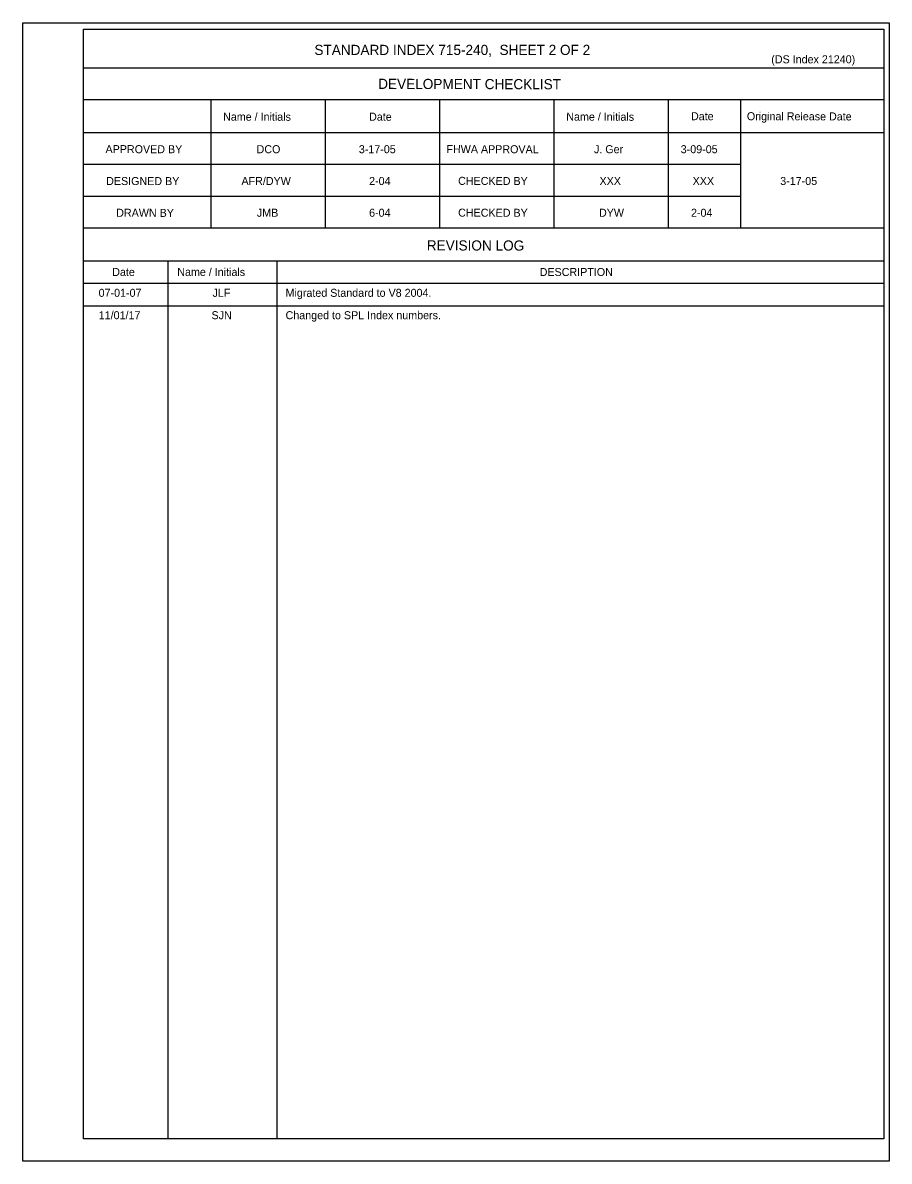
# Model space of a CAD drawing. Extents: x 112544 to 112597.1, y 111084 to 111107.1.
# Drawn here: x 112580.73 to 112597.09, y 111084.01 to 111105.51 of the extents above; entities that cross this region are included whole.
import ezdxf

# ---------------------------------------------------------------- set-up
doc = ezdxf.new("R2010")
doc.units = 0
for name, color, linetype in [('Border', 7, 'Continuous'), ('Dimension', 7, 'Continuous'), ('PlotBorder_dp', 7, 'Continuous'), ('TextStructures', 7, 'Continuous')]:
    doc.layers.add(name, color=color, linetype=linetype)

msp = doc.modelspace()

# ---------------------------------------------------------------- linework, layer by layer
at = {"layer": 'Border'}
for p, q in [((112596.991, 111104.654), (112581.881, 111104.654)), ((112596.991, 111104.054), (112581.881, 111104.054)), ((112584.281, 111104.054), (112584.281, 111101.633)), ((112586.441, 111104.054), (112586.441, 111101.633)), ((112588.601, 111104.054), (112588.601, 111101.633)), ((112590.761, 111104.054), (112590.761, 111101.633)), ((112592.921, 111104.054), (112592.921, 111101.633)), ((112594.282, 111104.054), (112594.282, 111101.633)), ((112596.991, 111103.433), (112581.881, 111103.433)), ((112594.282, 111102.833), (112581.881, 111102.833)), ((112594.282, 111102.233), (112581.881, 111102.233)), ((112596.991, 111101.633), (112581.881, 111101.633)), ((112596.991, 111101.012), (112581.881, 111101.012)), ((112583.471, 111101.012), (112583.471, 111084.432)), ((112585.528, 111101.012), (112585.528, 111084.432)), ((112596.991, 111100.589), (112581.881, 111100.589))]:
    msp.add_line(p, q, dxfattribs=at)
msp.add_lwpolyline([(112581.881, 111105.389), (112596.991, 111105.389), (112596.991, 111084.432), (112581.881, 111084.432)], close=True, dxfattribs=at)
at = {"layer": 'Dimension'}
msp.add_line((112581.881, 111100.167), (112596.991, 111100.167), dxfattribs=at)
at = {"layer": 'PlotBorder_dp'}
msp.add_line((112580.733, 111084.011), (112580.733, 111084.011), dxfattribs=at)
msp.add_lwpolyline([(112580.733, 111105.511), (112597.093, 111105.511), (112597.093, 111084.011), (112580.733, 111084.011)], close=True, dxfattribs=at)

# ---------------------------------------------------------------- texts
at = {"layer": 'TextStructures'}
for s, height, p in [('STANDARD INDEX 715-240,  SHEET 2 OF 2', 0.192, (112586.239, 111104.903)), ('(DS Index 21240)', 0.1512, (112594.866, 111104.746)), ('DCO', 0.1512, (112585.148, 111103.048)), ('3-17-05', 0.1512, (112587.078, 111103.048)), ('J. Ger', 0.1512, (112591.518, 111103.048)), ('3-09-05', 0.1512, (112593.156, 111103.048)), ('AFR/DYW', 0.1512, (112584.862, 111102.448)), ('2-04', 0.1512, (112587.272, 111102.448)), ('XXX', 0.1512, (112591.623, 111102.448)), ('XXX', 0.1512, (112593.381, 111102.448)), ('3-17-05', 0.1512, (112595.035, 111102.448)), ('JMB', 0.1512, (112585.153, 111101.848)), ('6-04', 0.1512, (112587.272, 111101.848)), ('DYW', 0.1512, (112591.613, 111101.848)), ('2-04', 0.1512, (112593.35, 111101.848)), ('DESCRIPTION', 0.1512, (112590.493, 111100.729)), ('07-01-07', 0.1512, (112582.165, 111100.336)), ('JLF', 0.1512, (112584.316, 111100.336)), ('Migrated Standard to V8 2004.', 0.1512, (112585.695, 111100.336)), ('11/01/17', 0.1512, (112582.167, 111099.913)), ('SJN', 0.1512, (112584.297, 111099.913)), ('Changed to SPL Index numbers.', 0.1512, (112585.695, 111099.913))]:
    msp.add_text(s, height=height, dxfattribs=at).set_placement(p)
for s, height, p in [('DEVELOPMENT CHECKLIST', 0.192, (112587.443, 111104.262)), ('Original Release Date', 0.1512, (112594.405, 111103.671)), ('Name / Initials', 0.1512, (112584.515, 111103.663)), ('Date', 0.1512, (112587.271, 111103.662)), ('Name / Initials', 0.1512, (112590.995, 111103.663)), ('Date', 0.1512, (112593.35, 111103.671)), ('APPROVED BY', 0.1512, (112582.295, 111103.05)), ('FHWA APPROVAL', 0.1512, (112588.732, 111103.05)), ('DESIGNED BY', 0.1512, (112582.307, 111102.448)), ('CHECKED BY', 0.1512, (112588.953, 111102.45)), ('DRAWN BY', 0.1512, (112582.497, 111101.848)), ('CHECKED BY', 0.1512, (112588.953, 111101.85)), ('REVISION LOG', 0.192, (112588.361, 111101.212)), ('Date', 0.1512, (112582.422, 111100.73)), ('Name / Initials', 0.1512, (112583.65, 111100.731))]:
    msp.add_text(s, height=height, rotation=359.8756, dxfattribs=at).set_placement(p)

doc.saveas('drawing.dxf')
